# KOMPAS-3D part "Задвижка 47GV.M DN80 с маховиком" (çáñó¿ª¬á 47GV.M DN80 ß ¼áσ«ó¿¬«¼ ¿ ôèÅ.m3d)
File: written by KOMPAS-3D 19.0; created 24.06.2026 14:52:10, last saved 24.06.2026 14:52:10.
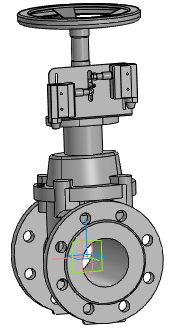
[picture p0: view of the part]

Document properties: Автор: Энергия; Полное имя файла: Z:\3.Личные\sachek\Dendor\3D для проектировщиков\2.7 Тип 47GV.M Задвижка клиновая фланцевая с обрезиненным клином\47GV.M DN80\Задвижка 47GV.M DN80 с маховиком.a3d

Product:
- Part/product: Задвижка 47GV.M DN80 с маховиком
    Масса: 22.0766
    source file: ..\47GV.M DN80\DR.47GVM.080.16.00.00 - Задвижка с обрезиненным клином DN80.spw
  - Component: Задвижка с обрезиненным клином DN80. Сборочный чертеж  | designation DR.47GVM.080.16.00.00СБ  | pos. 0  | Масса: 15.8764; Раздел спецификации: Документация; Форматы листов документа: 2xA3; source file: ..\47GV.M DN80\DR.47GVM.080.16.00.000 СБ - Задвижка с обрезиненным клином DN80.cdw
- Part/product: Задвижка 47GV.M DN80 с маховиком  | designation 01
    Масса: 15.8677
  - Component [standard]: Болт М10-6gx20-А2-70 ГОСТ 7798-70  | pos. 12  | Масса: 0.02379; Раздел спецификации: Стандартные изделия; Рассекать на разрезах: no
  - Component [standard]: Шайба1021695878  | pos. 20  | Материал: Сталь 12Х18Н10Т ГОСТ 5632-2014 (density 1000 kg/m3); Масса: 0.0121728; Раздел спецификации: Стандартные изделия; Рассекать на разрезах: no; additional columns: ГОСТ 6958-78; A 10.21
  - Component [detail]: Маховик 200  | pos. 15  | Масса: 0.448137; Раздел спецификации: Прочие изделия; source file: ..\47GV.M DN80\Маховик 200.m3d
  - Component [detail]: Крышка DN80  | pos. 4  | Материал: ВЧ50 ГОСТ 7293-85 (density 7200 kg/m3); Масса: 5.8711; Раздел спецификации: Детали; Форматы листов документа: 2xA3; source file: ..\47GV.M DN80\DR.47GVM.080.16.00.002 - Крышка.cdw, ..\47GV.M DN80\Крышка DN80.m3d
  - Component [detail]: Корпус DN80  | pos. 3  | Материал: ВЧ50 ГОСТ 7293-85 (density 7200 kg/m3); Масса: 13.7997; Раздел спецификации: Детали; Форматы листов документа: 2xA3; source file: ..\47GV.M DN80\DR.47GVM.050.16.00.001 - Корпус.cdw, ..\47GV.M DN80\DR.47GVM.080.16.00.001 - Корпус.cdw, ..\47GV.M DN80\Корпус DN80.m3d
  - Component [assembly]: Клин с направляющими  | designation DR.47GVM.080.16.01.000  | pos. 4  | Раздел спецификации: Сборочные единицы; Форматы листов документа: A4; source file: ..\47GV.M DN80\DR.47GVM.080.16.01.000 - Клин с направляющими.a3d, ..\47GV.M DN80\DR.47GVM.080.16.01.000 - Клин с направляющими.spw, ..\47GV.M DN80\DR.47GVM.080.16.01.000 СБ - Клин с направляющими.cdw
  - Component [detail]: Шпиндель  | pos. 5  | Материал: Сталь 20Х13 ГОСТ 5632 - 2014 (density 7670 kg/m3); Масса: 0.0942201; Раздел спецификации: Детали; Форматы листов документа: A3; source file: ..\47GV.M DN80\DR.47GVM.080.16.00.003 - Шпиндель.cdw, ..\47GV.M DN80\Шпиндель DN80.m3d
  - Component: Насадка для УКП  | designation DR.47GVM.UKP.100.16.00.001  | Материал: Сталь 08Х18Н10 ГОСТ 5632-2014 (density 7900 kg/m3); Масса: 0.534087; source file: ..\47GV.M DN80\DR.47GVM.UKP.100.16.00.001 - Насадка для УКП.cdw, ..\47GV.M DN80\DR.47GVM.UKP.100.16.00.001 Насадка для УКП.m3d
  - Component: Кронштейн  | designation DR.47GVM.UKP.100.16.00.002  | Материал: Ст3сп ГОСТ 380-2005 (density 7850 kg/m3); Масса: 0.15921; source file: ..\47GV.M DN80\DR.47GVM.UKP.100.16.00.002 - Кронштейн.cdw, ..\47GV.M DN80\DR.47GVM.UKP.100.16.00.002 - Кронштейн.m3d
  - Component: Контргайка  | designation DR.47GVM.UKP.100.16.00.003  | Материал: Сталь 08Х18Н10 ГОСТ 5632-2014 (density 7900 kg/m3); Масса: 0.103544; source file: ..\47GV.M DN80\DR.47GVM.UKP.100.16.00.003 - Контргайка.cdw, ..\47GV.M DN80\DR.47GVM.UKP.100.16.00.003 - Контргайка.m3d
  - Component: Винт установочный М6х45  | designation DR.47GVM.UKP.050.16.00.005  | Материал: Сталь 08Х18Н10 ГОСТ 5632-2014 (density 7900 kg/m3); Масса: 0.00994284; source file: ..\47GV.M DN50\DR.47GVM.UKP.050.16.00.005 Винт установочный.m3d
  - Component: Концевик AZ7311  | qty 2  | Масса: 0.377378; source file: ..\47GV.M DN50\Концевик AZ7311.m3d

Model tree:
1. Операция без истории:1

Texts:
  Точка начала. Х
  Точка начала. Y
  Точка начала. Z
